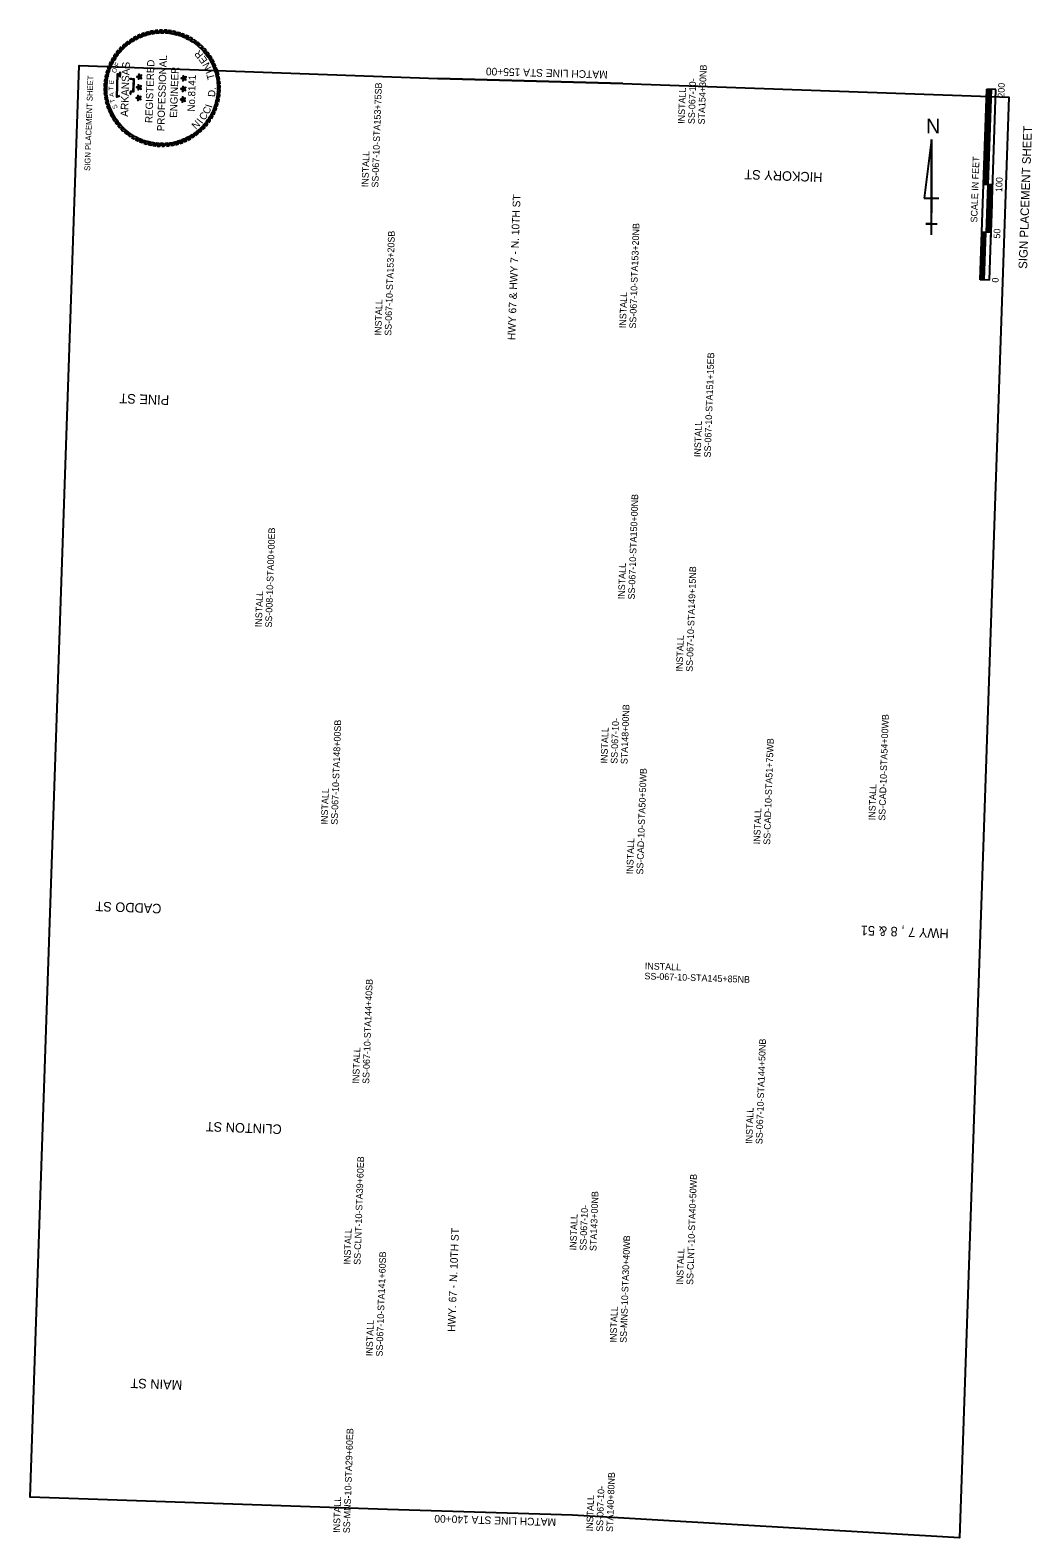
# Model space of a CAD drawing. Extents: x 992004 to 993053, y 1842727 to 1844306.
import ezdxf

# ---------------------------------------------------------------- set-up
doc = ezdxf.new("R2010")
doc.units = 0
for name, color, linetype in [('5', 7, 'Continuous'), ('63', 7, 'Continuous'), ('G-ANNO-SYMB', 7, 'Continuous'), ('G-ANNO-TEXT', 7, 'Continuous'), ('Level 10', 7, 'Continuous'), ('Plan Notes', 7, 'Continuous'), ('R_Annotation', 7, 'Continuous'), ('R_No Plot', 7, 'Continuous')]:
    doc.layers.add(name, color=color, linetype=linetype)

msp = doc.modelspace()

# ---------------------------------------------------------------- linework, layer by layer
at = {"layer": '5'}
for p, q in [((992625, 1844250.5), (992431.2, 1844255.7)), ((992572.2, 1842751.1), (992378.4, 1842757))]:
    msp.add_line(p, q, dxfattribs=at)
at = {"layer": '63'}
for p, q in [((992948.2, 1844192), (992940.5, 1844130.5)), ((992948.2, 1844092), (992948.2, 1844192)), ((992948.2, 1844192), (992948.2, 1844115.1)), ((992940.5, 1844130.5), (992955.9, 1844130.5)), ((992948.2, 1844092), (992948.2, 1844115.1)), ((992948.2, 1844103.5), (992942.4, 1844103.5)), ((992942.4, 1844103.5), (992954, 1844103.5)), ((992948.2, 1844092), (992948.2, 1844103.5))]:
    msp.add_line(p, q, dxfattribs=at)
at = {"layer": 'G-ANNO-SYMB'}
for points in [[(992119.6, 1844302), (992117.2, 1844301), (992115.1, 1844296.8), (992117.6, 1844298.1)], [(992124.1, 1844303.6), (992121.6, 1844302.8), (992119.2, 1844298.8), (992121.8, 1844299.9)], [(992128.7, 1844304.9), (992126.2, 1844304.2), (992123.4, 1844300.5), (992126.1, 1844301.3)], [(992133.4, 1844305.8), (992130.8, 1844305.3), (992127.8, 1844301.8), (992130.5, 1844302.5)], [(992138.1, 1844306.3), (992135.5, 1844306.1), (992132.2, 1844302.8), (992135, 1844303.2)], [(992142.9, 1844306.5), (992140.3, 1844306.4), (992136.8, 1844303.4), (992139.6, 1844303.6)], [(992147.7, 1844306.3), (992145.1, 1844306.4), (992141.3, 1844303.7), (992144.1, 1844303.7)], [(992152.4, 1844305.7), (992149.8, 1844306.1), (992145.9, 1844303.6), (992148.7, 1844303.4)], [(992157.1, 1844304.7), (992154.5, 1844305.3), (992150.4, 1844303.2), (992153.2, 1844302.7)], [(992161.7, 1844303.4), (992159.2, 1844304.2), (992154.9, 1844302.4), (992157.6, 1844301.7)], [(992166.1, 1844301.7), (992163.7, 1844302.7), (992159.3, 1844301.2), (992162, 1844300.4)], [(992099.8, 1844288.9), (992098, 1844287), (992097.6, 1844282.4), (992099.5, 1844284.5)], [(992103.3, 1844292.1), (992101.4, 1844290.4), (992100.7, 1844285.8), (992102.7, 1844287.8)], [(992107.1, 1844295.1), (992105, 1844293.5), (992103.9, 1844289), (992106.1, 1844290.8)], [(992111.1, 1844297.7), (992108.9, 1844296.3), (992107.5, 1844291.9), (992109.7, 1844293.5)], [(992115.3, 1844300), (992113, 1844298.8), (992111.2, 1844294.5), (992113.6, 1844296)], [(992170.5, 1844299.7), (992168.1, 1844300.9), (992163.6, 1844299.8), (992166.2, 1844298.7)], [(992174.6, 1844297.3), (992172.4, 1844298.7), (992167.8, 1844297.9), (992170.3, 1844296.7)], [(992178.6, 1844294.7), (992176.4, 1844296.2), (992171.8, 1844295.8), (992174.2, 1844294.3)], [(992182.3, 1844291.7), (992180.3, 1844293.4), (992175.6, 1844293.4), (992177.9, 1844291.7)], [(992185.8, 1844288.4), (992183.9, 1844290.3), (992179.3, 1844290.6), (992181.4, 1844288.8)], [(992189, 1844284.9), (992187.3, 1844286.9), (992182.7, 1844287.6), (992184.7, 1844285.6)], [(992088.6, 1844273.6), (992087.4, 1844271.3), (992088.5, 1844266.7), (992089.6, 1844269.3)], [(992090.9, 1844277.8), (992089.6, 1844275.5), (992090.3, 1844270.9), (992091.6, 1844273.4)], [(992093.6, 1844281.7), (992092.1, 1844279.6), (992092.5, 1844274.9), (992093.9, 1844277.3)], [(992096.6, 1844285.4), (992094.9, 1844283.4), (992094.9, 1844278.8), (992096.6, 1844281)], [(992191.9, 1844281.1), (992190.4, 1844283.2), (992185.8, 1844284.3), (992187.7, 1844282.2)], [(992194.6, 1844277.2), (992193.2, 1844279.4), (992188.7, 1844280.8), (992190.4, 1844278.5)], [(992196.9, 1844273), (992195.7, 1844275.3), (992191.4, 1844277.1), (992192.8, 1844274.7)], [(992198.9, 1844268.6), (992197.8, 1844271), (992193.7, 1844273.2), (992194.9, 1844270.6)], [(992082.6, 1844255.5), (992082.2, 1844253), (992084.6, 1844249), (992084.9, 1844251.8)], [(992083.5, 1844260.2), (992083, 1844257.7), (992085.1, 1844253.5), (992085.5, 1844256.3)], [(992084.9, 1844264.8), (992084.1, 1844262.3), (992085.9, 1844258), (992086.5, 1844260.8)], [(992086.5, 1844269.3), (992085.6, 1844266.8), (992087, 1844262.4), (992087.9, 1844265.1)], [(992118.8, 1844257.6), (992117.9, 1844258.3), (992116, 1844257.7), (992117.9, 1844257)], [(992118.8, 1844257.6), (992117.9, 1844257), (992117.8, 1844255), (992119, 1844256.6)], [(992118.8, 1844257.6), (992119.1, 1844258.6), (992118, 1844260.3), (992117.9, 1844258.3)], [(992118.8, 1844257.6), (992119.8, 1844257.6), (992121.1, 1844259.2), (992119.1, 1844258.6)], [(992118.8, 1844257.6), (992119, 1844256.6), (992120.9, 1844255.9), (992119.8, 1844257.6)], [(992165.3, 1844256), (992164.4, 1844256.7), (992162.5, 1844256.1), (992164.4, 1844255.4)], [(992165.3, 1844256), (992164.4, 1844255.4), (992164.3, 1844253.4), (992165.6, 1844255)], [(992165.3, 1844256), (992165.6, 1844257), (992164.5, 1844258.7), (992164.4, 1844256.7)], [(992165.3, 1844256), (992166.3, 1844256), (992167.6, 1844257.6), (992165.6, 1844257)], [(992165.3, 1844256), (992165.6, 1844255), (992167.5, 1844254.3), (992166.3, 1844256)], [(992200.5, 1844264.2), (992199.6, 1844266.6), (992195.7, 1844269.1), (992196.7, 1844266.4)], [(992201.8, 1844259.6), (992201.1, 1844262.1), (992197.3, 1844264.8), (992198.2, 1844262.1)], [(992202.7, 1844254.9), (992202.2, 1844257.4), (992198.7, 1844260.5), (992199.3, 1844257.7)], [(992203.2, 1844250.1), (992202.9, 1844252.7), (992199.7, 1844256), (992200.1, 1844253.2)], [(992082, 1844250.8), (992081.8, 1844248.2), (992084.6, 1844244.4), (992084.6, 1844247.3)], [(992081.8, 1844246), (992081.8, 1844243.4), (992084.8, 1844239.9), (992084.6, 1844242.7)], [(992081.9, 1844241.3), (992082.2, 1844238.7), (992085.5, 1844235.4), (992085, 1844238.2)], [(992118.4, 1844246.5), (992117.5, 1844247.2), (992115.6, 1844246.6), (992117.5, 1844245.9)], [(992118.4, 1844246.5), (992117.5, 1844245.9), (992117.4, 1844243.9), (992118.7, 1844245.5)], [(992118.4, 1844246.5), (992118.7, 1844247.5), (992117.6, 1844249.2), (992117.5, 1844247.2)], [(992118.4, 1844246.5), (992119.4, 1844246.5), (992120.7, 1844248.1), (992118.7, 1844247.5)], [(992118.4, 1844246.5), (992118.7, 1844245.5), (992120.6, 1844244.8), (992119.4, 1844246.5)], [(992164.9, 1844244.9), (992164.1, 1844245.6), (992162.1, 1844245), (992164, 1844244.3)], [(992164.9, 1844244.9), (992164, 1844244.3), (992163.9, 1844242.3), (992165.2, 1844243.9)], [(992164.9, 1844244.9), (992165.3, 1844245.9), (992164.1, 1844247.6), (992164.1, 1844245.6)], [(992164.9, 1844244.9), (992166, 1844244.9), (992167.2, 1844246.5), (992165.3, 1844245.9)], [(992164.9, 1844244.9), (992165.2, 1844243.9), (992167.1, 1844243.2), (992166, 1844244.9)], [(992203.4, 1844245.4), (992203.3, 1844248), (992200.3, 1844251.5), (992200.5, 1844248.7)], [(992202.6, 1844235.8), (992202.9, 1844238.4), (992200.5, 1844242.4), (992200.3, 1844239.6)], [(992203.1, 1844240.6), (992203.3, 1844243.2), (992200.6, 1844247), (992200.6, 1844244.1)], [(992082.5, 1844236.5), (992082.9, 1844234), (992086.5, 1844230.9), (992085.8, 1844233.7)], [(992083.4, 1844231.8), (992084, 1844229.3), (992087.8, 1844226.6), (992086.9, 1844229.3)], [(992084.6, 1844227.2), (992085.5, 1844224.8), (992089.5, 1844222.3), (992088.4, 1844224.9)], [(992118, 1844235.4), (992117.2, 1844236.1), (992115.2, 1844235.5), (992117.1, 1844234.8)], [(992118, 1844235.4), (992117.1, 1844234.8), (992117, 1844232.8), (992118.3, 1844234.4)], [(992118, 1844235.4), (992118.4, 1844236.4), (992117.2, 1844238.1), (992117.2, 1844236.1)], [(992118, 1844235.4), (992119.1, 1844235.4), (992120.3, 1844237), (992118.4, 1844236.4)], [(992118, 1844235.4), (992118.3, 1844234.4), (992120.2, 1844233.7), (992119.1, 1844235.4)], [(992164.5, 1844233.8), (992163.7, 1844234.5), (992161.7, 1844233.9), (992163.6, 1844233.2)], [(992164.5, 1844233.8), (992163.6, 1844233.2), (992163.6, 1844231.2), (992164.8, 1844232.8)], [(992164.5, 1844233.8), (992164.9, 1844234.8), (992163.7, 1844236.5), (992163.7, 1844234.5)], [(992164.5, 1844233.8), (992165.6, 1844233.8), (992166.8, 1844235.4), (992164.9, 1844234.8)], [(992164.5, 1844233.8), (992164.8, 1844232.8), (992166.7, 1844232.1), (992165.6, 1844233.8)], [(992196.6, 1844217.8), (992197.7, 1844220.1), (992196.6, 1844224.7), (992195.5, 1844222.1)], [(992198.6, 1844222.1), (992199.6, 1844224.5), (992198.1, 1844229), (992197.2, 1844226.3)], [(992200.3, 1844226.6), (992201, 1844229.1), (992199.3, 1844233.4), (992198.6, 1844230.6)], [(992201.6, 1844231.2), (992202.2, 1844233.7), (992200, 1844237.9), (992199.6, 1844235.1)], [(992086.3, 1844222.8), (992087.3, 1844220.4), (992091.5, 1844218.2), (992090.2, 1844220.8)], [(992088.2, 1844218.4), (992089.5, 1844216.1), (992093.8, 1844214.3), (992092.3, 1844216.7)], [(992090.6, 1844214.2), (992092, 1844212), (992096.4, 1844210.6), (992094.7, 1844212.9)], [(992093.2, 1844210.2), (992094.8, 1844208.2), (992099.3, 1844207.1), (992097.5, 1844209.2)], [(992185.3, 1844202.5), (992187.1, 1844204.3), (992187.5, 1844209), (992185.6, 1844206.8)], [(992188.6, 1844206), (992190.2, 1844208), (992190.2, 1844212.6), (992188.6, 1844210.3)], [(992191.5, 1844209.7), (992193, 1844211.8), (992192.7, 1844216.5), (992191.2, 1844214.1)], [(992194.2, 1844213.6), (992195.5, 1844215.9), (992194.8, 1844220.5), (992193.5, 1844218)], [(992096.1, 1844206.5), (992097.8, 1844204.5), (992102.4, 1844203.8), (992100.5, 1844205.8)], [(992099.3, 1844203), (992101.2, 1844201.1), (992105.9, 1844200.8), (992103.7, 1844202.6)], [(992102.8, 1844199.7), (992104.8, 1844198), (992109.5, 1844198), (992107.2, 1844199.7)], [(992106.6, 1844196.7), (992108.7, 1844195.2), (992113.3, 1844195.6), (992110.9, 1844197.1)], [(992110.5, 1844194), (992112.8, 1844192.7), (992117.4, 1844193.4), (992114.8, 1844194.7)], [(992114.7, 1844191.7), (992117, 1844190.5), (992121.5, 1844191.6), (992118.9, 1844192.7)], [(992161, 1844187.8), (992163.5, 1844188.6), (992165.9, 1844192.6), (992163.3, 1844191.5)], [(992165.5, 1844189.4), (992167.9, 1844190.4), (992170, 1844194.6), (992167.5, 1844193.3)], [(992169.9, 1844191.4), (992172.2, 1844192.6), (992173.9, 1844196.9), (992171.5, 1844195.4)], [(992174, 1844193.7), (992176.2, 1844195.1), (992177.7, 1844199.5), (992175.4, 1844197.9)], [(992178, 1844196.3), (992180.1, 1844197.9), (992181.2, 1844202.4), (992179, 1844200.6)], [(992181.8, 1844199.2), (992183.7, 1844201), (992184.5, 1844205.6), (992182.5, 1844203.6)], [(992119, 1844189.7), (992121.4, 1844188.7), (992125.8, 1844190.1), (992123.2, 1844191)], [(992123.5, 1844188), (992125.9, 1844187.2), (992130.3, 1844189), (992127.5, 1844189.7)], [(992128, 1844186.7), (992130.6, 1844186.1), (992134.7, 1844188.2), (992132, 1844188.7)], [(992132.7, 1844185.7), (992135.3, 1844185.3), (992139.3, 1844187.8), (992136.5, 1844188)], [(992137.5, 1844185.1), (992140.1, 1844185), (992143.8, 1844187.7), (992141, 1844187.7)], [(992142.2, 1844184.9), (992144.8, 1844184.9), (992148.4, 1844188), (992145.6, 1844187.8)], [(992147, 1844185.1), (992149.6, 1844185.3), (992152.9, 1844188.6), (992150.1, 1844188.2)], [(992151.7, 1844185.6), (992154.3, 1844186), (992157.3, 1844189.6), (992154.6, 1844188.9)], [(992156.4, 1844186.5), (992159, 1844187.2), (992161.7, 1844190.9), (992159, 1844190.1)]]:
    msp.add_lwpolyline(points, close=True, dxfattribs=at)
for points in [[(992098.1, 1844237.5), (992095, 1844236.2), (992095.8, 1844260.7), (992098.3, 1844258.5), (992098.4, 1844260.2), (992098.4, 1844261.6), (992098.6, 1844263)], [(992098, 1844237.8), (992095.4, 1844236.8), (992096.2, 1844259.9), (992098.7, 1844257.7), (992098.8, 1844260.2), (992098.8, 1844261.6), (992099, 1844262.9)], [(992108.8, 1844256.1), (992109.2, 1844255.6), (992109.8, 1844255.4), (992111.1, 1844255.2), (992112.5, 1844255.1), (992112, 1844242.2), (992110.1, 1844242.3), (992109.3, 1844242.3), (992109, 1844241.5), (992109, 1844239.7), (992108.6, 1844239.4)], [(992109.1, 1844256.4), (992109.4, 1844255.9), (992109.9, 1844255.8), (992111.2, 1844255.6), (992112.9, 1844255.5), (992112.4, 1844241.8), (992110.1, 1844241.9), (992109.6, 1844241.9), (992109.4, 1844241.4), (992109.3, 1844239.4), (992108.8, 1844239.1)]]:
    msp.add_lwpolyline(points, dxfattribs=at)
at = {"layer": 'Level 10'}
for p, q in [((993002, 1844124.8), (993006.1, 1844244.7)), ((993003.5, 1844144.7), (993006.9, 1844244.7)), ((993004.3, 1844144.7), (993007.7, 1844244.7)), ((993005.1, 1844144.7), (993008.5, 1844244.6)), ((993005.9, 1844144.7), (993009.3, 1844244.6)), ((993015.7, 1844244.4), (993006.1, 1844244.7)), ((993006.7, 1844144.6), (993010.1, 1844244.6)), ((993007.5, 1844144.6), (993010.9, 1844244.6)), ((993008.8, 1844044.5), (993015.7, 1844244.4)), ((992999.2, 1844044.8), (993004.7, 1844204.7)), ((993007.5, 1844144.6), (993009.5, 1844204.6)), ((993012.3, 1844144.4), (993002.7, 1844144.8)), ((993005.8, 1844094.6), (993007.5, 1844144.6)), ((993006.6, 1844094.6), (993008.3, 1844144.6)), ((993007.4, 1844094.6), (993009.1, 1844144.6)), ((993008.2, 1844094.6), (993009.9, 1844144.5)), ((993009, 1844094.5), (993010.7, 1844144.5)), ((993009.8, 1844094.5), (993011.5, 1844144.5)), ((993010.2, 1844084.5), (993011.6, 1844124.5)), ((992999.2, 1844044.8), (993000.6, 1844084.8)), ((993000, 1844044.8), (993001.8, 1844094.8)), ((993000.8, 1844044.8), (993002.6, 1844094.7)), ((993010.6, 1844094.5), (993001, 1844094.8)), ((993001.6, 1844044.7), (993003.4, 1844094.7)), ((993002.5, 1844044.7), (993004.2, 1844094.7)), ((993003.2, 1844044.7), (993005, 1844094.7)), ((993008.8, 1844044.5), (992999.2, 1844044.8))]:
    msp.add_line(p, q, dxfattribs=at)
at = {"layer": 'R_No Plot'}
msp.add_lwpolyline([(992378.4, 1842757), (992004.3, 1842769.8), (992055.8, 1844269.5), (992431.2, 1844255.7), (992625, 1844250.5), (993029.3, 1844236.2), (992977.5, 1842727.2), (992572.2, 1842751.1)], close=True, dxfattribs=at)

# ---------------------------------------------------------------- texts
at = {"layer": '63'}
msp.add_text('N', height=15.4, rotation=360, dxfattribs=at).set_placement((992942.5, 1844198.4))
at = {"layer": 'G-ANNO-SYMB'}
for s, height, rotation, p in [('F', 4.84, 63.3989, (992096.7, 1844267.5)), ('ARKANSAS', 7.89, 88.0361, (992106.8, 1844215.7)), ('REGISTERED', 7.64, 88.0361, (992132.3, 1844209.1)), ('PROFESSIONAL', 7.642, 88.0361, (992144.8, 1844200.5)), ('R', 7.64, 133.5141, (992186.1, 1844281)), ('E', 7.64, 125.6859, (992190.5, 1844274.8)), ('N', 7.64, 116.7394, (992194.5, 1844267)), ('O', 4.84, 69.2579, (992093.9, 1844261.1)), ('ENGINEER', 7.64, 88.0361, (992158.1, 1844214.6)), ('No.8141', 7.61, 88.0361, (992176.6, 1844221.1)), ('I', 7.64, 112.2662, (992196, 1844262.8)), ('T', 7.64, 104.8108, (992197.8, 1844255.8)), ('T', 4.84, 89.515, (992091.5, 1844243.2)), ('E', 4.84, 84.7081, (992091.8, 1844249.4)), ('A', 4.84, 96.7149, (992092.2, 1844236.9)), ('D', 7.64, 84.6812, (992197.9, 1844236.2)), ('.', 7.64, 92.8821, (992198.7, 1844244.1)), ('T', 4.84, 104.9376, (992093.5, 1844231)), ('S', 4.84, 107.8087, (992096.1, 1844224.8)), ('C', 7.64, 64.5516, (992191.2, 1844217.7)), ('I', 7.64, 72.3798, (992194.6, 1844224.6)), ('N', 7.64, 43.3037, (992177.8, 1844202)), ('I', 7.64, 52.2502, (992184.1, 1844208)), ('C', 7.64, 56.7234, (992186.9, 1844211.4))]:
    msp.add_text(s, height=height, rotation=rotation, dxfattribs=at).set_placement(p)
at = {"layer": 'G-ANNO-TEXT'}
for height, p in [(6, (992067.1, 1844159)), (9, (993048.3, 1844056.3))]:
    msp.add_text('SIGN PLACEMENT SHEET', height=height, rotation=88.0361, dxfattribs=at).set_placement(p)
at = {"layer": 'Level 10'}
for s, height, p in [('200', 7, (993024.5, 1844235.6)), ('SCALE IN FEET', 7.001, (992996.1, 1844104.9)), ('100', 7, (993022.2, 1844136.8)), ('50', 7, (993020.1, 1844088.1)), ('0', 7, (993018.4, 1844041.9))]:
    msp.add_text(s, height=height, rotation=88.0364, dxfattribs=at).set_placement(p)
at = {"layer": 'Plan Notes'}
for s, height, rotation, p in [('MATCH LINE STA 155+00', 8, 178.4486, (992609.2, 1844263.8)), ('HICKORY ST', 10, 177.8501, (992834.2, 1844157.3)), ('HWY 67 & HWY 7 - N. 10TH ST', 8, 87.8501, (992512.2, 1843981.7)), ('PINE ST', 10, 177.8501, (992150.1, 1843923.8)), ('CADDO ST', 10, 177.8501, (992142, 1843391.2)), ('HWY 7 , 8 & 51', 10, 177.8501, (992966.4, 1843365.1)), ('CLINTON ST', 10, 177.8501, (992268, 1843160.1)), ('HWY. 67 - N. 10TH ST', 8, 87.8501, (992449.4, 1842942.9)), ('MAIN ST', 10, 177.8501, (992163.8, 1842892.2)), ('MATCH LINE STA 140+00', 8, 178.266, (992555.2, 1842747.5))]:
    msp.add_text(s, height=height, rotation=rotation, dxfattribs=at).set_placement(p)
at = {"layer": 'R_Annotation'}
for s, rotation, p in [('SS-067-10-', 88.0361, (992700.2, 1844208)), ('STA154+30NB', 88.0361, (992710.7, 1844207.6)), ('SS-067-10-STA153+75SB', 88.0361, (992368.9, 1844141.5)), ('INSTALL', 88.0361, (992689.7, 1844208.3)), ('INSTALL', 88.0361, (992358.4, 1844141.9)), ('SS-067-10-STA153+20NB', 88.0361, (992638.7, 1843993.8)), ('SS-067-10-STA153+20SB', 88.0361, (992382.5, 1843986.3)), ('INSTALL', 88.0361, (992372, 1843986.6)), ('INSTALL', 88.0361, (992628.2, 1843994.2)), ('SS-067-10-STA151+15EB', 88.0361, (992717, 1843858.8)), ('INSTALL', 88.0361, (992706.5, 1843859.2)), ('SS-067-10-STA150+00NB', 88.0361, (992637.4, 1843710)), ('SS-008-10-STA00+00EB', 88.0361, (992257.4, 1843680.6)), ('INSTALL', 88.0361, (992626.9, 1843710.3)), ('SS-067-10-STA149+15NB', 88.0361, (992698.1, 1843634.3)), ('INSTALL', 88.0361, (992246.9, 1843681)), ('INSTALL', 88.0361, (992687.6, 1843634.6)), ('STA148+00NB', 88.0361, (992629.8, 1843537.6)), ('SS-067-10-STA148+00SB', 88.0361, (992326.3, 1843474.1)), ('INSTALL', 88.0361, (992608.8, 1843538.3)), ('SS-067-10-', 88.0361, (992619.3, 1843538)), ('SS-CAD-10-STA54+00WB', 88.0361, (992899.7, 1843478.4)), ('SS-CAD-10-STA51+75WB', 88.0361, (992779.2, 1843453.2)), ('SS-CAD-10-STA50+50WB', 88.0361, (992646.2, 1843421.9)), ('INSTALL', 88.0361, (992889.2, 1843478.8)), ('INSTALL', 88.0361, (992315.8, 1843474.4)), ('INSTALL', 88.0361, (992768.7, 1843453.6)), ('INSTALL', 88.0361, (992635.7, 1843422.3)), ('INSTALL', 358.0361, (992647.9, 1843322.8)), ('SS-067-10-STA144+40SB', 88.0361, (992359.3, 1843202.6)), ('SS-067-10-STA145+85NB', 358.0361, (992647.5, 1843312.3)), ('SS-067-10-STA144+50NB', 88.0361, (992771.1, 1843139.5)), ('INSTALL', 88.0361, (992348.8, 1843203)), ('INSTALL', 88.0361, (992760.6, 1843139.8)), ('SS-CLNT-10-STA39+60EB', 88.0361, (992350.2, 1843013.2)), ('SS-CLNT-10-STA40+50WB', 88.0361, (992698.6, 1842992.1)), ('STA143+00NB', 88.0361, (992597.3, 1843027.6)), ('SS-067-10-', 88.0361, (992586.8, 1843028)), ('INSTALL', 88.0361, (992576.3, 1843028.3)), ('INSTALL', 88.0361, (992339.7, 1843013.5)), ('SS-MNS-10-STA30+40WB', 88.0361, (992628.9, 1842931.4)), ('SS-067-10-STA141+60SB', 88.0361, (992373.4, 1842917.1)), ('INSTALL', 88.0361, (992688.1, 1842992.4)), ('INSTALL', 88.0361, (992618.4, 1842931.8)), ('INSTALL', 88.0361, (992362.9, 1842917.5)), ('SS-MNS-10-STA29+60EB', 88.0361, (992339.1, 1842732)), ('STA140+80NB', 88.0361, (992614.6, 1842733.3)), ('INSTALL', 88.0361, (992593.6, 1842734)), ('SS-067-10-', 88.0361, (992604.1, 1842733.6)), ('INSTALL', 88.0361, (992328.6, 1842732.4))]:
    msp.add_text(s, height=7, rotation=rotation, dxfattribs=at).set_placement(p)

doc.saveas('drawing.dxf')
